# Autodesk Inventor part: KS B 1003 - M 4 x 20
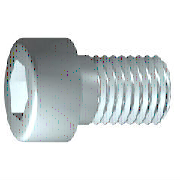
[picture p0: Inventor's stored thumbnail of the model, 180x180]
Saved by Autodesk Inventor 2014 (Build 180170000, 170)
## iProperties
IsCustomPart: 1
Company: 한국ATC센터
Created: 2009-02
Part Number: KS B 1003 - M 4 x 20
Material: 강철, 연강
Description: 6각머리 태핑 나사
Document SubType Name: Modeling
Standard: KS B 1003
Designer: KYOUNG IL JANG
Standards Organization: KS
Language: ko-KR
Size Designation: M 4 x 20
Categories: <MemberInstance><Categories><Category DisplayName="조임쇠" InternalName="e4da775c-781d-43d5-af7c-5136215cf5a6" Mnemonic="FSTN"><Category DisplayName="볼트" InternalN
Density: 7.86 g/cm^3
Mass: 2.82836 g
Surface Area: 4.06499 cm^2
Volume: 0.359842 cm^3
Vendor: CBT Solutions
Appearance: 강철
Author: KYOUNG IL JANG
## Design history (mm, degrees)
sketch "스케치1"
  geometry: L1 (-1, 0)-(20, 0); L2 (20, 0)-(20, 2); L3 (20, 2)-(1.75, 2); L4 (1.75, 2)-(1.32, 2); L5 (1.32, 2)-(0, 2); L6 (0, 2)-(0, 3.5); L7 (0, 3.5)-(-4, 3.5); L8 (-4, 3.5)-(-4, 1.732); L9 (-4, 1.732)-(-2, 1.732); L10 (-2, 1.732)-(-1, 0); L11 (-8.8, 0)-(24.8, 0) reference; L12 (0, -0.7)-(0, 4.2) reference; L13 (1.75, 2)-(0, 2)
  constraints: 22 end point, 6 parallel, 2 collinear, 2 perpendicular, 1 horizontal, 1 point on line
  dimensions: "d1" = 18.25 distance from line of L3.end L2 (= GEL); "d2" = 0.42952 distance of L4.end L3.end (computed from GAL); "d3" = 4 distance between parallel lines of L8 L6 (= KOH); "d4" = 2 distance of L8.end L9.end (= INTI); "d5" = 60 deg angle of L10 L1; "d6" = 4 diameter of L3 L1 (= GD); "d7" = 4 diameter of L5 L1 (= BDM); "d8" = 3.4641 diameter of L9 L1 (= 1.1547 x SW); "d9" = 7 diameter of L7 L1 (= KOD); "d26" = 20 distance between parallel lines of L12 L2 (= NLG)
revolve "본체" sketch "스케치1" stored, may be unused: angle "d10" = 90 deg
sketch "스케치2"
  geometry: L1 (0, -4.9)-(0, 4.9) reference; L2 (-4.9, 0)-(4.9, 0) reference; L3 (1.732, 0)-(0.866, -1.5); L4 (0.866, -1.5)-(-0.866, -1.5); L5 (-0.866, -1.5)-(-1.732, 0); L6 (-1.732, 0)-(-0.866, 1.5); L7 (-0.866, 1.5)-(0.866, 1.5); L8 (0.866, 1.5)-(1.732, 0); 2 further points
  constraints: 12 end point, 1 coincident, 1 horizontal alignment, 1 point on line, 12 other
extrude "슬롯" join sketch "스케치2" stored distance "d11" = 10; taper "d12" = 0 deg
workplane "Work Plane1"
fillet "Fillet2" dims "d30" = 0.1 (= R)
sketch "스케치4"
  geometry: C1 r 2.574 at (0, 0); 1 further point
  constraints: 1 centre point, 1 coincident
extrude "돌출3" cut sketch "스케치4" distance "d31" = 2; taper "d32" = 0 deg
chamfer "모따기3" distance "d33" = 0.4; stored, may be unused: second distance "d34" = 2, angle "d35" = 45 deg
body "Solid1"
fillet "모깎기1" dims "d17" = 0.4 (= RR)
feature "스레드" dims "d13" = 18.25 (= GEL), "d14" = 0
chamfer "모따기1" distance "d15" = 0.42941 (= -0.5 x SPD + 0.5 x GD); stored, may be unused: second distance "d16" = 0.42941 (= GUL), angle "d27" = 45 deg
other parameters: "GD" = 4 (= NND) [user parameter; used in 2 equation terms], "NLG" = 20 [user parameter; used in 1 equation term], "GEL" = 18.25 [user parameter; used in 2 equation terms], "KOD" = 7 [user parameter; used in 1 equation term], "KOH" = 4 [user parameter; used in 1 equation term], "INTI" = 2 [user parameter; used in 1 equation term], "GAL" = 0.42941 (= 0.61345 x PTC) [user parameter; used in 1 equation term], "GUL" = 0.42941 (= 0.61345 x PTC) [user parameter; used in 1 equation term], "BDM" = 4 (= NND) [user parameter; used in 1 equation term], "SW" = 3 [user parameter; used in 2 equation terms], "RR" = 0.4 [user parameter; used in 1 equation term], "SPD" = 3.14117 (= NND - 1.2269 x PTC) [user parameter; used in 1 equation term], "d19" = 0, "d28" = 0, "d29" = 0, "R" = 0.1 [user parameter; used in 1 equation term], "PHH" = 0.2 [user parameter], "GD1" = 3.14117 (= THREADDIA - 1.2269 x PTC) [user parameter], "THREADDIA" = 4 [user parameter; used in 1 equation term], "FAWI" = 45 deg [user parameter], "TPU" = 14.28571 (computed from PTC) [user parameter], "PTC" = 0.7 [user parameter; used in 5 equation terms], "NND" = 4 [user parameter; used in 3 equation terms], "TOA" = 30 deg [user parameter], "E0" = 3.465 (= 1.155 x SW) [user parameter]
